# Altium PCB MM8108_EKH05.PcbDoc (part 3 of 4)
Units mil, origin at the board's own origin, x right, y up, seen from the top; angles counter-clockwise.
Board outline 6023.62 x 3425.2 mil, 4 copper layers (Top Layer, Ground Plane, Middle Layer, Bottom Layer), stack 76.15 mil thick; 188 components, 156 nets, 687 pads, 1369 vias.
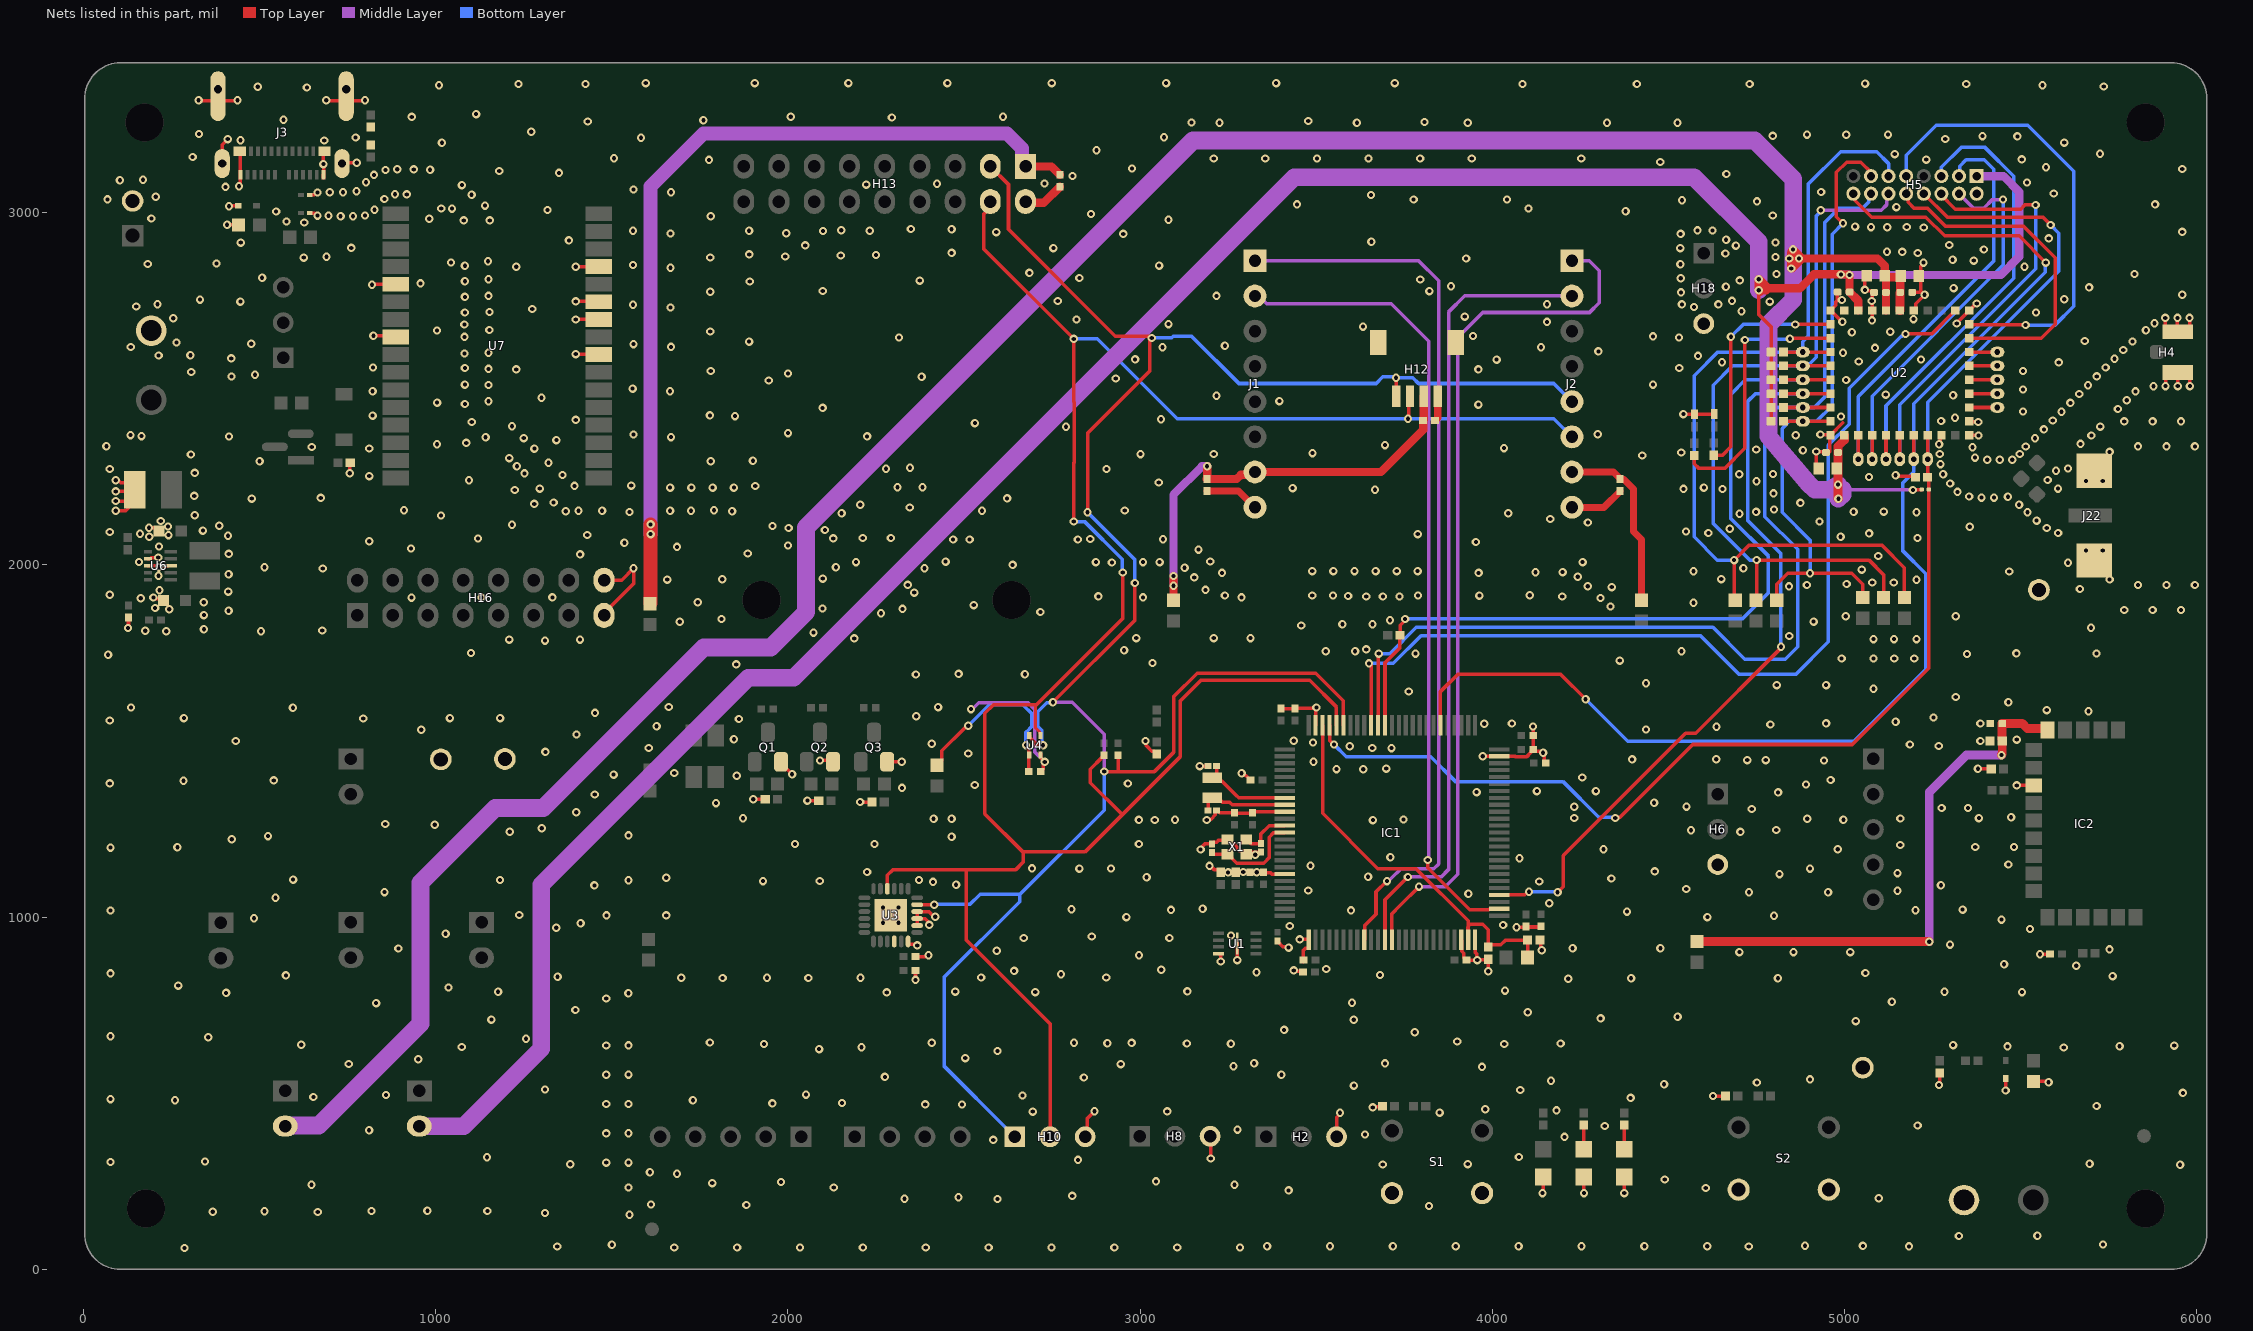
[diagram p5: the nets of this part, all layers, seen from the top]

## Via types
v1: diameter 23.62, hole 11.81, Top Layer to Bottom Layer, tented both sides, 1369 vias

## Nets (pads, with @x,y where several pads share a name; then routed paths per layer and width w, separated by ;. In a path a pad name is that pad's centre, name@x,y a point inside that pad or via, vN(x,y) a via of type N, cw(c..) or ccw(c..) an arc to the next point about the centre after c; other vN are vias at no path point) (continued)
GND: C1.1 C2.1 C3.1 C4.1 C5.1 C6.1 C7.1 C8.1 C9.2 C10.1 C11.1 C12.2 C13.2 C14.1 C15.1 C16.1 C17.1 C18.1 C19.2 C20.2 C21.1 C22.2 C23.2 C24.1 C25.1 C26.1 C27.2 C28.1 C29.2 C30.1 C31.2 C32.2 C33.2 C34.1 C35.1 C36.2 C37.1 C38.1 C39.1 C40.2 C41.1 C42.1 C43.1 C44.2 C45.1 C46.1 C47.1 C48.1 C49.2 D1.K D2.K D3.K D4.A D7.K D11.A D12.A D13.K H2.3 H4.2 H4.3 H5.2 H6.3 H8.3 H10.3 H11.1 H12.4 H12.5 H12.6 H13.2 H14.2 H15.1 H16.15 H16.16 H18.3 IC1.10 IC1.19 IC1.26 IC1.48 IC1.50 IC1.74 IC1.99 IC2.8 J1.8 J2.8 J3.A1 J3.A12 J3.B1 J3.B12 J3.SH1 J3.SH2 J3.SH3 J3.SH4 J22.2 Q1.S Q2.S Q3.S R8.2 R49.2 R52.2 R65.1 R66.1 R67.1 R69.2 R70.2 R72.2 R75.2 S1.3 S1.4 S2.3 S2.4 TP1.1 TP2.1 TP3.1 TP4.1 U1.4 U1.9 U2.1 U2.3 U2.11 U2.20 U2.23 U2.26 U2.30 U2.38 U3.4 U3.6 U3.8 U3.9 U3.10 U3.25 U4.4 U6.2 U6.3 U6.8 U7.5 U7.8 U7.24 U7.26 U7.27 U7.29 VS1.A X1.2 X1.4 | length 7032.6
  Top Layer w10: v1(91.38,2153.74) 120,2153.74 C49.2@145.52,2179.25 ; v1(91.38,2181.3) 133.71,2181.3 145.52,2193.11 129.77,2208.86 v1(91.38,2208.86) ; v1(91.38,2240.35) 93.99,2237.75 100.88,2237.75 105.86,2232.76 120,2232.76 C49.2@146.5,2206.27 ; v1@127.79,1820.2 R72.2@127.79,1850.43 ; C49.2@146.5,2179.25 C49.2@146.5,2206.27 ; U6.3@182.91,1997.36 206.79,1997.36 210.72,1993.43 v1(214.41,1993.43) ; U6.2@182.91,2017.05 189.44,2017.05 192.63,2020.24 211.6,2020.24 v1(212.35,2020.98) ; v1(186.15,2105.38) 204.82,2105.38 C42.1@214.41,2095.79 ; v1(198.28,1907.26) 201.92,1903.62 222.79,1903.62 C41.1@227,1899.41 ; v1@214.41,1991.38 v1(214.41,1993.43) ; U6.8@240,1997.36 239.92,1997.28 219.45,1997.28 215.59,1993.43 v1(214.41,1993.43) ; v1(326.77,3318.9) 327.36,3318.31 436.42,3318.31 v1(437.01,3318.9) ; J3.SH2@393.7,3139.37 393.7,3192.91 v1(409.45,3208.66) ; v1(407.75,2965.55) 439.93,2965.55 C40.2@440.47,2965 ; v1(412.84,3018) 413.83,3018.99 438.37,3018.99 VS1.A@439.36,3019.98 ; v1(441.44,3074.8) 441.44,3078.49 445.16,3082.21 445.16,3106.97 J3.A12@445.67,3107.48 ; J3.A12@445.67,3112.21 J3.B1@445.67,3181.31 ; D12.A@640,3050 D12.A@640.91,3049.09 ; D11.A@642.2,2999.22 643.11,2998.32 656.48,2998.32 662.68,2992.11 v1@666.37,2992.11 ; D12.A@642.2,3050 643.11,3050.91 654.62,3050.91 660.79,3057.07 v1(664.47,3057.07) ; J3.A1@681.1,3098.43 681.38,3098.7 681.38,3106.97 J3.A1@681.89,3107.48 681.41,3107.96 681.41,3137.49 v1(681.1,3137.8) 681.1,3171.65 J3.B12@683.86,3174.41 ; v1(688.98,3318.9) 689.57,3318.31 798.62,3318.31 v1(799.21,3318.9) ; J3.SH1@733.07,3107.28 733.07,3130.71 744.09,3141.73 v1(775.59,3141.73) ; v1(755.76,2260.06) 756.54,2260.85 756.54,2289.22 R75.2@757.32,2290 ; v1@787.43,1566.7 790.32,1563.81 v1(794.01,1563.81) ; R70.2@814.21,3243.46 R70.2@815,3242.68 ; R69.2@815,3192.32 R69.2@820.27,3197.59 ; v1(818.9,2795.28) 820.47,2796.85 U7.5@886.38,2796.85 ; v1(822.83,2650.68) 882.54,2650.68 U7.8@886.38,2646.85 ; v1(1397.64,2598.43) 1461.18,2598.43 U7.24@1462.76,2596.85 ; v1(1397.64,2696.85) U7.26@1462.76,2696.85 ; v1(1397.64,2748.03) 1461.58,2748.03 U7.27@1462.76,2746.85 ; v1(1397.64,2846.46) 1462.36,2846.46 U7.29@1462.76,2846.85 ; H16.15@1477.76,1856.69 1477.76,1862.6 1561.57,1946.42 v1(1561.57,1990.43) 1527.84,1956.69 H16.16@1477.76,1956.69 ; H16.15@1497.1,1849.61 H16.15@1500.25,1846.46 ; v1(1901.57,1334.65) R65.1@1935.43,1334.65 ; Q1.S@1980.33,1440.94 1980.33,1435.69 1997.64,1418.39 1999.14,1418.39 2011.81,1405.72 v1(2011.81,1405.51) ; v1(2055.12,1330.71) R66.1@2087.4,1330.71 ; v1(2090.65,1444.88) 2124.02,1444.88 Q2.S@2127.95,1440.94 ; v1(2204.72,1326.77) R67.1@2238.58,1326.77 ; Q3.S@2281.51,1440.94 v1(2322.83,1440.94) ; U3.6@2341.02,930.98 2341.02,925.25 2342.76,923.5 2359.81,923.5 2363.31,920 v1(2367,920) ; v1(2362,822) C38.1@2362,849 ; C37.1@2362,888 2391.31,888 2395.31,892 v1(2399,892) ; U3.8@2366.61,976.26 U3.9@2366.61,995.94 ; v1(2401,978) 2398.39,980.61 2398.39,986.86 2389.31,995.94 U3.9@2366.61,995.94 ; v1(2418,1001) 2414.31,1001 2400.41,1014.91 2367.33,1014.91 U3.10@2366.61,1015.63 U3.9@2366.61,995.94 ; U4.4@2716.54,1464.57 2717.44,1463.66 2717.44,1451.85 v1@2728.37,1440.92 ; C39.1@2718.11,1413.39 2724.93,1420.2 2724.93,1433.01 2727.7,1435.79 2727.7,1440.25 v1@2728.37,1440.92 ; v1(2728.8,1440.92) v1@2728.37,1440.92 ; H10.3@2848.9,371.72 2848.9,427.64 v1(2870.08,448.82) ; v1(3015.19,1500.19) 3017.61,1497.78 3017.61,1486.52 3033.14,1470.98 3040.04,1470.98 3047.24,1463.78 R8.2@3047.24,1462.99 ; v1(3169.17,1428.67) 3169.4,1428.9 3192.29,1428.9 C25.1@3192.52,1429.13 ; v1(3171.52,1192.19) 3171.52,1195.88 3180.47,1204.83 ; 3180.47,1204.87 3183.67,1208.07 C23.2@3203.74,1208.07 3203.74,1209.65 3207.01,1212.91 3216.85,1212.91 3222.16,1218.22 3245.78,1218.22 X1.4@3248.03,1220.47 3257.8,1210.71 3261.73,1210.71 3267.54,1204.9 3269.32,1204.9 3275.76,1198.45 3275.76,1194.9 3281.77,1188.9 3291.42,1188.9 X1.2@3301.18,1179.13 3306.69,1184.65 C22.2@3342.52,1184.65 ; v1(3188.98,1275.59) 3191.58,1278.2 3201.23,1278.2 3213.36,1290.33 3213.36,1299.88 C26.1@3216.63,1303.15 ; v1(3196.85,1145.67) 3198.99,1145.67 3209.52,1135.14 3221.14,1135.14 3228.35,1127.94 C17.1@3228.35,1127.56 ; v1(3200,315) 3200,363.78 H8.3@3214.17,377.95 ; C26.1@3216.93,1303.15 3218.5,1303.15 3225.13,1296.53 C3.1@3267.72,1296.53 ; U1.4@3222.64,895.67 3228.46,895.67 3228.54,895.59 v1(3228.54,874.21) ; C17.1@3232.28,1127.56 C21.1@3271.65,1127.56 3350.39,1127.56 3351.97,1125.98 3370.08,1125.98 3373.89,1122.17 3409.8,1122.17 IC1.19@3409.92,1122.05 ; C3.1@3267.72,1296.85 3270.08,1294.49 3316.54,1294.49 C2.1@3318.9,1296.85 ; v1(3275.59,877.95) U1.9@3275.59,925.2 ; v1(3287.84,1408.64) 3291.53,1408.64 3299.02,1401.14 3300.86,1401.14 3312,1390 C1.1@3313,1390 ; C2.1@3318.9,1296.53 3321.58,1299.21 IC1.10@3409.92,1299.21 ; C24.1@3389.76,932.68 3389.76,931.1 3404.87,915.99 3418.65,915.99 v1(3421.26,913.39) ; C14.1@3400,1592 C11.1@3440,1592 3441.5,1593.5 3498.5,1593.5 v1(3500,1595) 3498.94,1593.94 3498.94,1545.71 IC1.99@3498.03,1544.8 ; v1(3435.72,848.85) 3438.09,846.48 C5.1@3461.22,846.48 ; v1(3452.76,937.01) 3453.67,937.92 3477.44,937.92 3478.35,937.01 IC1.26@3478.35,935.51 3478.35,912.38 3477.44,911.48 3469.17,911.48 3463.31,905.62 C4.1@3463.31,874.02 ; H2.3@3557.38,376.69 3557.38,432.21 3566.93,441.76 v1(3566.93,444.88) ; v1(3660,460) 3661.3,461.3 3686.1,461.3 C19.2@3687.4,462.6 ; IC1.48@3911.42,935.51 3912.32,934.61 3912.32,903.79 3918.78,897.34 3918.78,885.16 3925.98,877.95 v1(3956.69,877.95) ; IC1.50@3950.79,935.51 3951.69,934.61 3951.69,899.44 3954.76,896.37 3954.76,879.88 v1(3956.69,877.95) ; v1(3972.44,1456.69) IC1.74@4019.21,1456.69 4064.55,1456.69 4066.43,1454.82 4096.42,1454.82 4109.43,1467.82 4109.43,1471.38 4114.43,1476.38 C8.1@4115.43,1476.38 ; v1(3988.19,846.46) C13.2@3988.19,880.31 3987.01,879.13 3957.87,879.13 v1(3956.69,877.95) ; v1(4068.34,971.2) 4068.74,971.59 C7.1@4134.97,971.59 ; C6.1@4100,972.61 4139.61,972.61 C7.1@4140,973 ; v1(4115.09,1541.3) 4115.26,1541.13 4115.26,1515.92 C10.1@4115.43,1515.75 ; C10.1@4115.75,1515.75 4115.75,1476.38 4120.75,1471.38 4135.59,1471.38 4140.05,1466.91 v1(4143.74,1466.91) 4146.35,1464.31 4146.35,1441.84 C15.1@4151.18,1437.01 ; C12.2@4134.45,935.04 4137.45,932.04 4137.45,908.64 v1(4140.05,906.03) ; v1(4141.73,216.54) 4143.7,218.5 D3.K@4143.7,262.2 ; D2.K@4258.86,262.2 4258.86,217.52 v1(4259.84,216.54) ; v1(4374.02,216.54) D1.K@4374.02,262.2 ; v1(4541.97,2428.12) 4542.13,2428.28 4629.36,2428.28 D7.K@4629.53,2428.44 ; v1(4625.98,492.13) C20.2@4661.81,492.13 ; C29.2@4918.96,2283.43 v1(4918.96,2321.88) ; v1@4919.45,2321.4 C30.1@4946.22,2321.4 ; C29.2@4929.79,2283.43 C29.2@4932.78,2280.44 ; v1@4929.79,2321.88 v1@4930.27,2321.4 ; v1(4930.86,2370.17) 4958.57,2370.17 U2.11@4960.14,2368.6 ; C30.1@4957.05,2321.4 4957.05,2365.51 U2.11@4960.14,2368.6 ; C44.2@4979.75,2774.54 4978.57,2773.36 4978.57,2750.29 4974.79,2746.51 4974.79,2737.58 U2.20@4959.65,2722.44 v1@4988.2,2693.89 ; 4994.86,2404 4994.86,2403.33 U2.11@4960.14,2368.6 ; C31.2@5062.18,2812.91 5057.07,2807.81 v1(5057.07,2780.86) 5059.68,2778.26 5077.35,2778.26 C43.1@5082.55,2773.05 ; v1(5077.33,2694.1) 5077.54,2694.31 5077.54,2722.23 U2.23@5077.76,2722.44 C43.1@5077.76,2771.91 ; v1(5144.54,2254.39) 5147.14,2251.78 5198.56,2251.78 C32.2@5200.64,2253.86 ; U2.26@5195.87,2722.44 5201.48,2728.06 5201.48,2741.66 v1(5226.88,2767.06) 5215.22,2778.73 5215.22,2846.06 5223.59,2854.44 v1(5223.59,2858.13) ; C28.1@5198.37,2773.62 5216.64,2773.62 ; v1(5267.72,523.62) 5269.69,525.59 C36.2@5269.69,557.87 ; v1(5267.97,2342.35) 5270.58,2344.95 5270.58,2368.87 U2.3@5273.2,2371.49 ; v1@5324.21,2692.66 5324.21,2693.31 5372.87,2741.96 v1(5374.68,2741.96) ; U2.1@5349.99,2367.9 5350.22,2367.66 5379.1,2367.66 v1(5379.55,2367.22) ; U2.38@5350.3,2406.95 5350.56,2406.69 5378.41,2406.69 v1(5379.2,2405.9) ; v1(5377.95,1421.26) R49.2@5415.75,1421.26 ; v1(5456.69,507.87) D4.A@5456.69,541.34 ; v1(5488.19,1374.02) IC2.8@5536.22,1374.02 ; R52.2@5535.43,533.46 5576.77,533.46 v1(5578.74,531.5) ; v1(5554.29,894.54) 5554.52,894.77 5582.45,894.77 C35.1@5582.68,895 ; v1(5910,2701.22) 5910,2678.07 5925.67,2662.4 H4.2@5944.88,2662.4 ; v1(5910.76,2507.44) 5910.76,2530.59 5926.43,2546.26 H4.3@5944.88,2546.26 ; v1(5944.5,2701.22) 5944.5,2662.78 H4.2@5944.88,2662.4 ; v1(5945.26,2507.44) 5945.26,2545.88 H4.3@5944.88,2546.26 ; v1(5979,2701.22) 5979,2678.07 5963.33,2662.4 H4.2@5944.88,2662.4 ; v1(5979.76,2507.44) 5979.76,2530.59 5964.09,2546.26 H4.3@5944.88,2546.26 ; C49.2@146.5,2193.11 C49.2@146.5,2206.27 ; C49.2@146.5,2193.11 C49.2@146.5,2206.27 ; C49.2@146.5,2193.11 C49.2@146.5,2206.27 ; C49.2@146.5,2193.11 C49.2@146.5,2206.27 ; C49.2@146.5,2193.11 C49.2@146.5,2206.27
  Top Layer w20: C46.1@3188.98,2209.77 3279.4,2209.77 J1.8@3325.59,2163.58 ; C48.1@3837,2410 3838,2410 3844.65,2416.65 H12.4@3844.65,2479 ; J2.8@4225.59,2163.58 4317.02,2163.58 4362.2,2208.77 C47.1@4362.2,2209.77
  Top Layer w23.62: H13.2@2674.41,3031.5 2677.48,3028.43 2726.53,3028.43 C45.1@2771.65,3073.55
  Middle Layer w10: v1(2519.68,1590.55) 2523.37,1590.55 2541.08,1608.26 2681.74,1608.26 2700,1590 2700,1469.72 v1(2728.8,1440.92)
  other v1: 286.55,60.7 1677.17,62.24 1855.64,62.24 2034.12,62.24 2212.6,62.24 2391.08,62.24 2569.55,62.24 2748.03,62.24 2926.51,62.24 3104.99,62.24 3283.46,62.24 1345,65 4727.36,65.11 3360.3,65.54 3538.78,65.54 3717.26,65.54 3895.73,65.54 4074.21,65.54 4252.69,65.54 4431.17,65.54 4609.64,65.54 5182.36,65.4 5051.47,66.91 4887.17,67.35 1500,70 5733.15,70.84 5324.1,94.78 5546.93,95.48 1550,155 1310.31,159.96 665.17,163.15 366.82,163.79 514.08,165.06 817.53,165.7 1146.47,165.7 976.26,166.34 3820,180 1881.89,182.81 1611,184 2595,200 2330.71,200.79 5096.67,202.13 2484.25,204.72 2807.09,208.66 3421.26,224.41 4605.35,231.22 1547.24,232.28 2129.92,232.28 647.23,240.26 3267.72,240.16 1785,245 1980.31,248.03 3045,250 4489.15,255.03 1685.04,271.65 1607.81,275.59 5952.26,297.03 3688.62,297.74 1381.72,298.33 3929.66,298.89 5695.12,300.09 1484.25,303.15 1547.24,303.15 76.54,304.95 344.75,306.3 2823.37,311.05 1145.38,318.25 4075.01,319.11 2582.9,367.67 4204.4,376.3 3637.87,383.09 1484.25,386.28 1547.24,386.39 810.79,395.26 3276.28,396.88 4318.48,407 5206.87,408.76 3850,445 2695.03,447.83 3076.74,448.71 4181.52,451.55 3979.26,454.59 5715.02,463.86 2493.96,467.92 2389.76,468.5 1484.25,469.42 1547.24,469.63 1955.74,471.26 2153.54,472.44 259.77,480.23 1730.03,480.42 76.54,483.43 4392.17,486.84 652.62,489.49 2665.91,493.86 858.78,495.35 2051.18,496.06 5959.94,501.23 4079.01,509.38 1310.02,510.77 3606.53,521.79 4487.35,525.66 4750.61,530.59 4165.86,535.74 4901.57,539.37 2840,545 2275.08,546.52 1484.25,552.55 1547.24,552.87 3400.65,552.8 3970,575 3264.75,576.68 2944.88,582.68 753.19,583.35 3695,585 3323.42,585.44 950.13,596.76 2503.03,599.84 2595,620 2088.47,625.21 5621.73,629.82 2208.76,630.63 1073.68,631.6 5462.09,633.21 5780.4,633.7 5935.68,635.15 1484.25,635.68 1547.24,636.11 5307.78,636.61 618.27,637.77 1932.09,639.76 4033.34,639.87 3257.32,640.49 2906.64,641.86 3132.4,641.36 4193.5,641.38 2407.97,643.29 2975.47,643.19 1778.22,644.25 2811.93,643.46 3900.07,647.06 1256.4,655 354,659 76.54,661.9 3779.53,673.23 3408.42,680 5031.5,704.72 1158,709 3606.3,708.66 4307.09,712.6 4525.52,717.18 4100,730 1396.32,736.49 830.71,755.91 3600.94,756.8 5133.86,759.84 1484.25,769.1 1546.8,784.08 405,785 2280.33,786.57 2701.84,787.21 5503.33,787.03 5283.03,788 1177.05,788.43 2474.76,788.59 3133.86,789.21 4035.43,791.34 1036.45,800.41 269.07,805.53 4215,825 4393.7,826.77 4810.1,826.77 1696.79,827.77 1814.53,827.35 1940.22,828.18 2057.96,827.35 2205.95,828.13 2548.29,828.72 2903.31,828.83 1346,831 5760.51,832.64 574.45,834.74 3680.74,835.85 2775.14,838.04 76.54,840.38 5058.61,841.26 3330.21,843.77 2641.89,847.38 3059.47,850.56 3527.92,852.84 5657.13,861.91 5452.39,866.37 2996.35,891.79 4700.79,900.79 4854.33,900.79 5015.75,900.79 2592.5,904.65 5751.52,908.56 894,911 4227.62,911.67 4476.58,911.87 5299.07,921.94 2669.29,940.94 3082.68,940.94 2862.2,944.88 3257.83,947.83 1028.07,952.94 5525.89,966.35 1342.02,970 3424.4,974.65 4030.12,977.83 1411.26,982.46 2270.15,984.13 2313.46,984.13 5444.8,992.94 483.91,996.88 2960.63,1000 4610,1000 4799.21,1003.94 1485,1005 1654.6,1005 1237.27,1006.23 4381.89,1015.75 76.54,1018.86 3598.41,1019.19 5200.79,1019.68 3087.21,1020.74 5334.75,1021.35 2804.8,1022.54 3177.17,1023.62 2270.15,1027.44 2313.46,1027.44 4161.21,1039.41 545.24,1054.94 3931.5,1066.57 854.59,1071.11 4728.35,1070.87 4952.76,1070.87 5150,1075 3477.1,1075.45 4550,1080 1450.35,1090.17 5272.81,1090.55 2477.32,1092.1 2411.52,1100.13 4132.91,1101.45 1929.13,1102.36 2090.23,1102.39 1547.34,1104.95 1182.21,1105.51 2371.94,1105.58 595.12,1106.46 4337.6,1109.49 1654.6,1111.72 3018.06,1113.34 3646.93,1114.48 4814.96,1122.05 5150,1125 3249.49,1127.22 2224.74,1128.19 3292.43,1128.04 3330.56,1127.49 4460.63,1129.92 2827.19,1137.8 2917.24,1137.94 4901.57,1137.8 2692.64,1138.38 3483.44,1145.69 5464.57,1149.61 4076.84,1167.07 3710,1170 3326.69,1177.16 4314.96,1192.91 4980.31,1192.91 76.54,1197.34 266.41,1198.54 5370.63,1199.21 5480.52,1198.96 5157.48,1204.72 2019.68,1207.81 2245.64,1207.81 2996.06,1207.81 421,1221 2464.57,1228.35 524,1230 1547.34,1232.07 4703.74,1242.13 1209.93,1242.38 4563.62,1246.49 4805.55,1247.38 1301.13,1252.45 997.31,1262.52 856.69,1264.2 2996.14,1276.16 3041.24,1275.59 3660.42,1275.44 3098.68,1276.47 4996.06,1276.4 3747.25,1277.35 2413.39,1279.53 2464.57,1279.53 4893.7,1279.53 5157.88,1279.86 1872.1,1280.56 5380.76,1281.07 4232.28,1281.61 5472.44,1283.46 1398.68,1297.67 4736.22,1307.09 5275,1310 5350,1310 4232.28,1313.29 4550.53,1313.76 1795.61,1323.7 4458.91,1324.8 1451.35,1348.04 3955,1355 4811.02,1354.33 4125.98,1357.68 4293.6,1357.68 2323.66,1367.09 2530.11,1375.18 4890.2,1376.47 74.68,1379.7 2964.78,1379.43 283.67,1387.08 539.93,1388.41 4959.95,1389.39 4254.92,1396.65 1854.33,1401.57 1505.08,1404.5 1677.17,1409.45 3557.16,1420.14 3633.03,1419.85 3698.27,1421.62 3491.76,1441.06 4940.94,1444.88 4723.43,1445.84 4775.76,1445.84 4396.33,1447.83 4635.3,1448.25 2511.81,1464.57 1311.2,1469.21 1604.87,1480.16 3658.51,1480.06 3713.12,1479.77 3595,1485 5266.89,1485.93 5185,1490 2408.31,1492.14 3490.33,1495.59 432.38,1499.94 5385,1500 3435.72,1500.72 5488.19,1503.94 1846.44,1505.25 1399.43,1518.36 959,1532 4435.77,1532.86 4635.84,1540.59 1627,1542 4788.98,1546.72 3976.56,1548.85 4055,1549.92 4947.26,1550.15 5385,1550 5144.57,1554.79 74.68,1558.18 1860.53,1562.5 285,1565 1040,1565 1182.88,1565 5251.97,1566.93 2364.25,1570.25 1452,1580 5692.17,1584.73 5573.65,1587.77 135,1595 594.49,1594.49 2426.13,1596.24 1661.49,1596.66 5464.57,1610.24 5315,1625 3762.06,1640.42 5081.69,1648.62 4807.09,1658.71 4947.26,1658.71 4435.77,1664.04 2363.15,1689.04 2672.51,1689.64 2484.37,1690.54 1853.22,1717.57 3034.85,1721.52 4361.1,1728.35 4991.14,1734.25 5081.69,1734.25 5140.75,1734.25 5197.45,1734.25 70,1745 5347.2,1747.27 3781.48,1748.03 5487.19,1748.78 5714.58,1748.54 1100,1750 3526.58,1754.69 3610,1755 4536.42,1754.92 2954.37,1757.89 3641.58,1760.24 1310,1785 1208.66,1787.81 1409.45,1787.81 5081.69,1789.37 5139.76,1789.37 5203.74,1789.37 2188.33,1791.38 2988.67,1792.15 3208.66,1792.15 3312.81,1792.15 4842.49,1798.03 2072.22,1807.79 234.83,1811.77 504.05,1811.51 175.44,1813.05 677.95,1813.72 341.63,1817.32 126.53,1820.67 5698.98,1821.46 3457.12,1827.83 3573.84,1831.65 3659.41,1831.65 1692.91,1838.58 4911.66,1839.06 3708.86,1842.91 1811.02,1846.46 5002.95,1854.33 5314.96,1854.33 341.63,1857.48 2264.16,1862.59 2716.54,1866.14 411.94,1869.94 5793.31,1872.05 5874.02,1872.05 5954.72,1872.05 243.57,1874.22 2325.05,1875.27 2097.87,1876.18 203.43,1877.54 4335,1881.82 2527.56,1885.83 4570.87,1892.53 341.21,1893.8 1743.94,1893.91 162.32,1905.21 4306.55,1906.08 931.38,1906.98 1130.08,1907.46 1331.15,1907.93 3007.81,1907.81 3287.4,1907.92 4197.85,1910.25 2881.25,1910.61 3641.58,1910.48 3688.83,1910.48 3736.07,1910.48 3590.22,1911.67 3962.83,1912.7 3240.16,1913.39 3488.19,1913.39 3547.24,1913.39 3788.67,1913.39 4105.91,1913.96 74.68,1915.13 2358.27,1921.26 410.97,1924.06 215.76,1927.83 3185.04,1929.13 5667.53,1931.39 4338.58,1937.01 4842.02,1938.95 4270.3,1939.31 2340.2,1943.26 4892.61,1942.83 5832.68,1942.91 5913.39,1942.91 5994.09,1942.91 5005.34,1945.96 5078.14,1950.26 5139.2,1949.87 1657.45,1958.27 5203.74,1957.68 1813.47,1959.13 5751.97,1958.66 4649.61,1959.65 2098.81,1961.01 3153.54,1964.57 4242.11,1966.5 212.74,1969.01 411.98,1973.43 3232.28,1977.42 3960.63,1977.42 4122.29,1979.25 4199.15,1979.59 4570.87,1982.09 5467.14,1981.39 3488.19,1982.42 3548.23,1982.42 3608.27,1982.42 3668.31,1982.42 3728.35,1982.42 3787.4,1982.42 5048.39,1986.67 679.06,1989.84 2387.45,1990.5 4712.27,1990.59 3125.98,1992.13 514.02,1993.17 2136.01,1993.54 2637.8,2000 5633.86,2005.91 2919.56,2007.01 2192.91,2007.87 2874.02,2007.87 3007.81,2007.87 3055.12,2007.87 4255.91,2007.87 157.38,2008.42 2447.44,2009.26 3198.67,2009.69 5094.97,2025.02 1410,2030 412.49,2031.39 1885.98,2032.31 5685.04,2041.34 5732.28,2041.34 3165.35,2043.31 929.96,2046.41 1685.04,2051.18 214.41,2052.48 2000,2055.12 1535.43,2062.99 3952.81,2065 811.02,2066.93 2468.88,2071.94 2515.75,2072.05 2822.83,2072.05 3064.87,2072.62 2858.22,2073.73 1120,2075 2128.56,2075.37 2212.09,2076.21 2292.02,2076.2 5206.4,2076.14 186.61,2080.1 4988.39,2080.04 410,2082.58 241.3,2084.46 1430,2085 3788.02,2087.27 160.27,2088.25 5069.29,2089.62 4612.87,2090.62 5605.78,2090.33 74.68,2093.61 4549.6,2095 338.99,2097.29 2104.75,2099.21 4673.7,2102.66 2001.86,2104.53 5573.47,2104.88 5354.99,2108.15 240.04,2108.82 385.55,2111.02 1956.24,2110.69 1216.54,2114.17 4270.69,2120.25 4928.15,2123.03 219.17,2124.72 5544.8,2125.7 4164.17,2130.29 1015,2140 315.63,2140.87 4701.28,2145.02 2152.38,2146.83 4044.68,2146.41 1550,2150 5203.54,2149.69 5518.69,2149.66 4748.37,2150.63 5025.16,2150.92 5110.77,2151.12 1369.03,2152.45 1841.47,2152.32 1405.51,2153.54 1472.44,2153.54 1665.35,2153.54 1724.41,2153.54 2550.83,2153.89 2955.85,2154.27 910,2155 1790,2155 4799.24,2157.12 2345.86,2162.98 2205.22,2170.66 5495.19,2170.56 1279.53,2173.23 4873.96,2176.18 1334.65,2177.17 477.47,2188.11 2622.05,2188.98 673.52,2190.33 5388.39,2190.91 5423.82,2190.91 5353.1,2194.13 5463.15,2193.47 314.42,2195.9 4798.02,2203.02 5320.23,2207.34 1224.41,2212.6 3666.68,2213.32 4652.95,2215.28 4542.39,2215.82 1295.28,2216.54 5605.62,2216.53 3432.69,2217.88 1665.35,2219.27 1725.72,2219.27 1786.09,2219.27 1846.46,2219.27 4600.21,2219.32 2311.02,2220.47 2381.89,2220.47 1907.05,2224.12 1393.7,2224.41 1555,2225 5299.13,2231.1 3052.6,2234.04 4749.35,2237.44 5685.04,2238.19 5732.28,2238.19 1094.49,2240.16 5575.92,2241.17 5068.68,2249.41 811.02,2251.97 1360,2255 4700.36,2257.46 4796.33,2258.26 5279.4,2257.58 1251.97,2259.84 315.63,2261.22 5599.95,2267.22 74.68,2272.09 2904,2272.2 2278.36,2272.82 5633.86,2273.62 2346.46,2275.59 1230.36,2280.12 5271.91,2286.12 1320,2290 500.13,2294.19 1780.76,2294.4 1900.35,2295.71 5404.58,2298.51 5440.01,2298.51 5475.44,2298.51 1208.66,2303.15 5369.67,2304.58 4425.04,2310.36 304.74,2313.22 3000.55,2314.44 3208.66,2314.96 5269.89,2314.78 5496.75,2315.07 3488.82,2317.33 4535.88,2319.01 5751.97,2320.87 4881.11,2325.34 4748.92,2327.4 1280,2330 811.02,2330.71 4032.63,2331.59 5362.79,2334.21 648.05,2334.6 5514.03,2335.93 64.98,2336.7 5832.68,2336.61 5913.39,2336.61 5994.09,2336.61 3695,2340 1003.55,2342.52 5669.29,2343.61 1086.61,2346.46 1342.52,2354.33 1250,2360 5540.28,2359.73 1141.73,2362.2 1667.74,2362.74 413.19,2364.56 2224.63,2364.95 164.87,2365.52 4861.1,2368.11 5700.17,2367.44 133.62,2368.4 1561.55,2370.39 4298.9,2370.75 2000,2374.02 5565.34,2384.79 2789.21,2392.27 5725.22,2392.49 1216.54,2393.7 2530.53,2402.44 1102.36,2405.51 5273.7,2408.28 5793.31,2407.48 5874.02,2407.48 5954.72,2407.48 5590.39,2409.84 1397.52,2411.7 3059.06,2413.39 5313.22,2417.65 4989.38,2421.47 1849.46,2422.37 820.84,2423.86 1778.13,2424.51 5615.45,2434.9 5505.91,2435.64 5775.33,2442.6 2098.42,2445.78 3960,2455 1082.68,2456.69 5640.5,2459.95 1003.94,2460.63 1149.61,2464.57 3395,2465 5800.39,2467.66 1300.21,2474.32 3216.54,2480.31 5307.7,2481.55 5116.23,2483.49 5665.56,2485.01 820.94,2492.97 1665.11,2492.84 5825.44,2492.71 5506.24,2498.03 1558.93,2500.5 5876.44,2507.28 5690.61,2510.06 1149.61,2510.5 1082.68,2511.81 4455.71,2511.81 1945.46,2523.51 5004.07,2525.07 2930.47,2529.27 2379.46,2533.92 420.21,2534.92 5715.67,2535.12 487.05,2539.86 2000,2543.31 306,2547.61 1780.76,2550.67 5505.91,2550.4 1228.35,2555.12 3960,2555 1149.61,2556.43 1082.68,2559.06 4530.13,2559.1 5740.72,2560.17 822.11,2560.57 5607.48,2574.87 4651.54,2575.3 5039.83,2577.22 4011.81,2582.68 5216.26,2583.16 2985.39,2583.51 5765.78,2585.23 419.54,2586.35 4583.4,2593.48 213.28,2594.37 303.33,2595.03 1081.46,2600.19 4995.24,2602.13 1149.61,2602.36 4300.52,2606.28 5790.83,2610.28 5085.68,2616.06 3062.99,2618.11 4137.8,2618.11 134.34,2618.72 1667.74,2619.01 3240.16,2622.05 1561.55,2626.66 476.31,2627.76 264.19,2631.26 1889.76,2633.86 5816.76,2634.43 5681.46,2635.85 2314.96,2645.67 4529.27,2645.46 1081.46,2647.43 4455.71,2648.72 3944.88,2649.61 5020.26,2660.66 5129.16,2662.06 1779.45,2662.37 1003.55,2665.35 5855,2666.22 1152.35,2666.67 3632.19,2676.47 1081.22,2682.23 3080.36,2683.42 5317.83,2685.23 5879.46,2686.23 4155,2690 4993.4,2690.37 2818.9,2696.85 5195.13,2697.68 255,2700 3921.26,2704.72 1082.68,2716.54 5542.79,2716.35 1152.62,2718.11 4707.02,2720.27 1274.13,2726.51 1666.43,2730.71 4572.24,2732.02 149.84,2733.81 1560.24,2738.37 210,2740 4155,2740 4537.68,2739.67 4641.36,2739.67 445.41,2747.45 4786.97,2747.5 2765.9,2749.27 5076.57,2749.09 4679.82,2749.53 4991.78,2752.06 330.99,2753.01 5623.03,2754.05 1082.68,2760.83 1149.61,2763.78 3216.54,2763.78 5958.26,2766.88 4535.02,2773.61 1779.45,2775.39 2098.59,2777.79 3820.71,2777.29 5309.24,2785.84 5693.83,2787.96 4662.46,2789.52 3882.18,2791.25 956.69,2799.21 1082.68,2805.12 1891.62,2804.51 2374.02,2807.09 4701.91,2807.87 3795,2810 1149.61,2811.02 4534.41,2813.98 507.17,2815 2827.2,2814.44 4806.05,2825.7 5822.6,2825.97 2685.34,2828.95 1666.43,2843.73 5510.32,2846.21 1228.35,2846.46 1082.68,2849.41 3053.61,2849.67 1560.24,2851.39 4533.49,2853.74 182.26,2854.35 377.7,2855.65 1043.31,2858.27 1148.4,2862.2 5366.46,2863.72 5306.39,2866.42 3925.2,2870.08 625.31,2872.34 1779.45,2872.64 690,2875 4803.24,2874.35 1992.31,2875.63 2149.58,2878.51 2250,2880 1889.93,2881.6 4661.18,2883.93 5207.43,2885.24 2464.57,2885.83 5120.14,2888.96 5163.19,2888.66 5394.88,2895.4 760,2900 2753.39,2899.32 4532.88,2899.31 2048.86,2907.18 4690.9,2906.34 5296.86,2908.34 446.46,2914.99 4803.63,2915.02 3656.21,2917.5 1377.95,2921.26 4663.32,2922.91 5579.31,2927.02 2951.73,2939.75 4534.1,2939.68 1666.43,2940.98 1995.18,2941.35 2591.42,2944.67 5958.26,2945.35 2099.15,2947.87 1560.24,2948.64 1889.76,2948.82 2232.28,2948.82 2151.38,2949.96 4581.94,2949.78 4624.76,2949.48 2464.57,2952.76 2348.91,2953.52 5224.39,2957.96 5074.68,2958.84 5120.7,2958.46 5175.98,2959.42 5029.43,2960.36 626.85,2971.91 576.2,2975.01 1079.65,2978.1 1153.25,2978.18 3080,2980 192.59,2983.2 981.57,2982.55 730,2990 765,2990 1780.76,2989.61 664.53,2991.45 695.71,2991.36 799.05,2991.92 4795.73,2991.68 2860.26,2996 546.88,3003.31 4377.95,3003.94 826.14,3008.12 1317.11,3007.78 1015.7,3011.96 1046.24,3011.51 4102.36,3011.81 5146.67,3015.74 1140,3020 3444.88,3023.62 5881.08,3023.46 4751.02,3032.02 4537.94,3035.28 68.07,3037.82 3776.21,3037.5 4041.21,3037.5 854.07,3038.57 205,3045 3655,3050 1101.8,3050.62 884.51,3052.25 917.75,3051.97 5593.15,3054.15 699.19,3057.9 736.9,3057.9 1667.74,3057.94 4932.94,3058.59 775.16,3060.69 1561.55,3065.6 403.05,3073.19 1074.24,3078.18 2222.34,3079.53 2423.25,3082.17 2728.35,3082.68 5517.49,3085.48 802.2,3086.38 103.31,3091.86 168.7,3093.54 2807.56,3104.18 824.75,3107.28 4663.89,3109.78 1349.97,3112.91 1180.44,3118.17 857.55,3121.3 984.08,3121.86 890.66,3123.2 937.71,3122.98 5958.26,3123.83 2976.8,3125.21 5571.14,3128.85 4476.38,3143.84 1775.5,3149.94 5231.36,3150.44 5502.38,3151.31 3208.66,3153.54 3355.12,3153.54 3501.57,3153.54 3648.03,3153.54 3794.49,3153.54 3940.94,3153.54 4251.97,3153.54 1506.09,3154.37 309.92,3157.83 5141.8,3166.11 5724.61,3167.01 2876,3177 1017.48,3198.33 5622.99,3198.69 683.37,3204.8 445.52,3205.44 5285.13,3209.14 1582.68,3212.6 772.48,3213.33 3067.35,3213.9 5490.16,3216.54 4795.73,3217.9 5390.85,3217.35 5004.3,3220.94 4892.91,3221.57 5122.78,3221.41 327.72,3223.12 1271.12,3229.87 3225,3255 3615,3255 3930,3255 4325,3255 4525,3255 3145.67,3255.91 3806.79,3257.51 1431.45,3258.79 3476.84,3259.98 1759.84,3262.22 567.92,3263.76 2295,3270 932.05,3271.93 2007.87,3272.19 2610.24,3272.19 1114.73,3279.81 634.06,3355.07 494.65,3357.25 5735.54,3358.31 1009.36,3361.65 5561.47,3361.65 1235,3365 1425,3365 4085,3365 4410,3365 4730,3365 5345,3365 5057.82,3366.3 1596.28,3367.81 1905.48,3367.81 2171.32,3367.81 2452.46,3367.81 2748.91,3367.81 3073.4,3367.75 3385.83,3367.75 3722.39,3367.75
I2C_SCL: H10.1 H12.1 H13.3 IC1.95 J2.5 R82.2 U3.11 U4.2 | length 6493.4
  Top Layer w10: U3.11@2366.61,1035.31 2414.68,1035.31 v1(2415,1035) ; H13.3@2574.41,3131.5 2625.98,3079.92 2625.98,2952.76 2929.13,2649.61 3027.56,2649.61 v1@3027.56,2644.29 ; U4.2@2685.04,1515.75 2685.94,1514.84 2685.94,1510.91 2707.42,1489.43 2723.03,1489.43 v1(2724.27,1488.19) ; v1(2751.97,1610.24) 2985,1843.27 2985,1948.67 v1(2984.84,1948.83) ; v1(2850.39,2149.61) 2850.39,2374.02 3027.56,2551.18 v1@3027.56,2644.29 ; v1(2897.64,1413.39) 2937.01,1413.39 ; R82.2@2937.01,1459.38 2937.01,1413.39 ; v1(3032.88,2644.29) v1@3027.56,2644.29 ; IC1.95@3576.77,1544.8 3576.77,1614.17 3498.03,1692.91 3161.42,1692.91 3094.49,1625.98 3094.49,1467.51 3040.36,1413.39 2937.01,1413.39 ; v1(3725.85,2531.18) 3726.19,2530.84 3726.19,2479.34 H12.1@3726.54,2479
  Middle Layer w10: v1(2751.97,1610.24) 2807.09,1610.24 2897.64,1519.69 v1(2897.64,1413.39)
  Bottom Layer w10: v1(2415,1035) 2416,1036 2516,1036 2545.5,1065.5 2657.93,1065.5 2657.93,1043.93 2443,829 2443,577.39 2629.92,390.47 H10.1@2657.48,390.47 ; 2657.93,1064.27 2897.64,1303.98 v1(2897.64,1413.39) ; v1(2724.27,1488.19) 2721.67,1490.8 2721.67,1499.66 2720.47,1500.86 2720.47,1529.91 2708.79,1541.59 2708.79,1567.08 2708.79,1582.81 2734.38,1608.39 2750.13,1608.39 v1(2751.97,1610.24) ; v1(2850.39,2149.61) 2985,2015 2985,1948.98 v1(2984.84,1948.83) ; v1(3032.88,2644.29) 3088.46,2644.29 3093.78,2649.61 3145.67,2649.61 3280.28,2515 3670,2515 3688.78,2533.78 3723.24,2533.78 v1(3725.85,2531.18) 3726.35,2531.68 3773.32,2531.68 3790,2515 4174.17,2515 J2.5@4225.59,2463.58
I2C_SDA: H10.2 H12.2 H13.4 IC1.96 J2.6 R85.2 U3.16 U4.1 | length 6810.3
  Top Layer w8: 2702.56,1603.27 2702.56,1600.2 2702.56,1537.6 2714.63,1525.53 2714.63,1521.59 U4.1@2716.54,1519.68
  Top Layer w10: U3.16@2281.96,1080.59 2281.96,1118.96 2297,1134 2505.92,1134 ; H13.4@2574.41,3031.5 2574.41,3014.5 2555.12,2995.2 2555.12,2897.64 v1(2811.02,2641.73) 2811.02,2463.39 2812.02,2462.39 2812.02,2290.34 2811.02,2289.34 v1(2811.02,2123.14) ; 2667.35,1185 2667.35,1155.59 2645.75,1134 2505.92,1134 ; 2702.56,1600.2 2950.18,1847.82 v1(2950.18,1978.48) ; 2702.56,1603.27 2583.58,1603.27 2559.06,1578.74 2559.06,1293.01 2667.06,1185 2843.02,1185 3114.17,1456.16 3114.17,1614.17 3172.42,1672.42 3481.12,1672.42 3557.09,1596.46 IC1.96@3557.09,1544.8 ; H10.2@2744.09,380.66 2744.09,696.85 2505.92,935.02 2505.92,1134 ; R85.2@2897.64,1459.38 2897.64,1458.38 2892.64,1453.38 2891.64,1453.38 2858.27,1420.01 2858.27,1381.89 2947.25,1292.91 ; v1(3760,2415) 3762.61,2417.61 3762.61,2475.7 H12.2@3765.91,2479
  Bottom Layer w10: v1(2811.02,2123.14) 2841.86,2123.14 2948.54,2016.46 2948.54,1980.11 v1(2950.18,1978.48) ; v1(2811.02,2641.73) 2878.27,2641.73 3105,2415 v1(3760,2415) 4174.17,2415 J2.6@4225.59,2363.58
LED_G: R17.1 U2.19 | length 668.9
  Top Layer w10: R17.1@4628.08,2311.24 4653.12,2311.24 4676.83,2334.96 v1(4676.83,2647.87) ; v1(4859.73,2682.52) 4860.28,2683.07 U2.19@4959.65,2683.07
  Bottom Layer w10: v1(4676.83,2647.87) 4711.48,2682.52 v1(4859.73,2682.52)
LED_R: R21.1 U2.18 | length 749.3
  Top Layer w10: R21.1@4572.58,2310.73 4572.58,2287.53 4586.29,2273.82 4659.25,2273.82 4716.6,2331.18 4716.6,2468.06 v1(4716.6,2638.63) ; v1(4844.28,2641.87) 4845.19,2642.79 4958.73,2642.79 U2.18@4959.65,2643.7
  Bottom Layer w10: v1(4716.6,2638.63) 4718.22,2640.25 4842.66,2640.25 v1(4844.28,2641.87)
MIKRO_AN: IC1.34 J1.1 | length 2561.3
  Top Layer w10: IC1.34@3635.83,935.51 3636.73,936.42 3636.73,975.9 3669.29,1008.46 3669.29,1071.93 3699.72,1102.36 v1(3700.79,1102.36)
  Middle Layer w10: J1.1@3325.59,2863.58 3789.96,2863.58 3847.03,2806.51 3847.03,1151.06 3833.76,1137.8 3740.16,1137.8 3711.54,1109.17 3711.28,1109.17 3704.47,1102.36 v1(3700.79,1102.36)
MIKRO_INT: IC1.37 J2.2 | length 2281.6
  Top Layer w10: IC1.37@3694.88,935.51 3694.88,1049.21 v1(3759.84,1114.17)
  Middle Layer w10: v1(3759.84,1114.17) 3854.33,1114.17 3875.31,1135.15 3875.31,2717.83 3921.06,2763.58 J2.2@4225.59,2763.58
MIKRO_PWM: IC1.38 J2.1 | length 2453.9
  Top Layer w10: IC1.38@3714.57,935.51 3714.57,1009.84 3736.89,1032.17 v1(3791.34,1086.61)
  Middle Layer w10: v1(3791.34,1086.61) 3866.14,1086.61 3901.59,1122.06 3901.59,2645.69 3972.44,2716.54 4275.59,2716.54 4303.15,2744.09 4303.15,2834.65 4274.21,2863.58 J2.1@4225.59,2863.58
MIKRO_RST: IC1.52 J1.2 | length 2296.6
  Top Layer w10: v1(3816.26,1162.1) 3816.26,1140.07 3935.49,1020.84 3989.32,1020.84 3991.19,1022.72 4018.31,1022.72 IC1.52@4019.21,1023.62
  Middle Layer w10: J1.2@3325.59,2763.58 3336.91,2763.58 3358.95,2741.55 3712.8,2741.55 3819.26,2635.08 3819.26,1174.73 3818.87,1174.34 3818.87,1164.71 v1(3816.26,1162.1)
MM_BUSY: IC1.91 U2.29 | length 2736
  Top Layer w10: v1(3649.61,1720.47) 3655.51,1714.57 IC1.91@3655.51,1544.8 ; v1(5172.49,2655.7) 5247.23,2655.7 U2.29@5313.98,2722.44
  Bottom Layer w10: v1(3649.61,1720.47) 3718.41,1720.47 3797.15,1799.21 4590.55,1799.21 4700.79,1688.98 4861.22,1688.98 4953.6,1781.35 4953.6,2340.3 5012.5,2399.2 5012.5,2501.24 5160.77,2649.51 5162.62,2649.51 5168.81,2655.7 v1(5172.49,2655.7)
MM_DBG_RX: H5.9 U2.31 | length 1326.9
  Top Layer w10: U2.31@5353.35,2683.07 5354.37,2682.05 5512.54,2682.05 v1(5513.57,2681.03)
  Bottom Layer w10: H5.9@5174.41,3103.74 5174.41,3162.6 5259.84,3248.03 5519.69,3248.03 5649.95,3117.76 5649.95,2734.07 5596.91,2681.03 v1(5513.57,2681.03)
MM_DBG_TX: H5.10 U2.32 | length 959.8
  Top Layer w10: H5.10@5178.76,3057.73 5179.8,3056.69 5179.8,3029.63 5196.33,3013.11 5233.85,3013.11 5284.95,2962.01 5506.74,2962.01 5597.14,2871.61 5597.14,2683.4 5557.44,2643.7 U2.32@5353.35,2643.7
MM_GPIO_3: U2.21
MM_GPIO_6: pad.31@5433.07,2604.33 U2.33 | length 77.4
  Top Layer w10: U2.33@5353.35,2604.33 pad.31@5430.73,2604.33
MM_GPIO_7: pad.31@5433.07,2564.96 U2.34 | length 91.5
  Top Layer w10: U2.34@5353.35,2564.96 pad.31@5444.88,2564.96
MM_GPIO_8: pad.31@5433.07,2525.59 U2.35 | length 91.5
  Top Layer w10: U2.35@5353.35,2525.59 pad.31@5444.88,2525.59
MM_GPIO_9: pad.31@5433.07,2486.22 U2.36 | length 91.5
  Top Layer w10: U2.36@5353.35,2486.22 pad.31@5444.88,2486.22
MM_GPIO_10: pad.31@5433.07,2446.85 U2.37 | length 91.5
  Top Layer w10: U2.37@5353.35,2446.85 pad.31@5444.88,2446.85
MM_JTAG_TCK: H5.5 pad.31@5117.13,2300.2 U2.7 | length 1299.9
  Top Layer w10: pad.31@5117.13,2309.06 U2.7@5117.13,2368.11
  Bottom Layer w10: pad.31@5117.13,2300.2 5117.13,2451.77 5479.57,2814.22 5479.57,3103.81 5398.35,3185.04 5330.71,3185.04 5274.41,3128.74 H5.5@5274.41,3103.74
MM_JTAG_TDI: H5.3 pad.31@5038.39,2300.2 U2.9 | length 1185.7
  Top Layer w10: pad.31@5038.39,2309.06 U2.9@5038.39,2368.11
  Bottom Layer w10: pad.31@5038.39,2300.2 5038.39,2477.95 5423.08,2862.65 5423.08,3122.93 5395.93,3150.09 5344.42,3150.09 5326.28,3131.94 5326.28,3105.61 H5.3@5324.41,3103.74
MM_JTAG_TDO: H5.4 pad.31@5077.76,2300.2 U2.8 | length 1102.7
  Top Layer w10: pad.31@5077.76,2309.06 U2.8@5077.76,2368.11
  Middle Layer w10: H5.4@5324.41,3053.74 5365.5,3012.65 5394.93,3012.65 5419.5,3037.22 v1(5449.08,3037.22)
  Bottom Layer w10: pad.31@5077.76,2300.2 5077.76,2479.21 5450.23,2851.68 5450.23,3036.06 v1(5449.08,3037.22)
MM_JTAG_TMS: H5.6 pad.31@5156.5,2300.2 U2.6 | length 1232.3
  Top Layer w10: pad.31@5156.5,2309.06 U2.6@5156.5,2368.11 ; H5.6@5272.26,3051.59 5313.68,3010.16 5499.6,3010.16 5511.35,3021.91 v1(5542.04,3021.91)
  Bottom Layer w10: pad.31@5156.5,2300.2 5156.5,2455 5542.04,2840.54 v1(5542.04,3021.91)
MM_RESET_N: C32.1 H5.8 IC1.97 pad.31@5235.24,2300.2 R16.1 U2.4 | length 3894.5
  Top Layer w10: IC1.97@3537.4,1544.8 3537.4,1502.6 v1(3550,1490) ; v1(4348.31,1281.61) 4350.92,1284.22 4362.96,1284.22 4568.9,1490.16 5021.65,1490.16 5125.98,1594.49 5238.39,1706.89 5238.39,2223.42 ; H5.8@5224.41,3053.74 5291.59,2986.55 5563,2986.55 v1(5584.45,2965.11) ; U2.4@5235.24,2368.11 5235.24,2298.23 5235.24,2261.07 C32.1@5236.66,2259.65 ; 5238.19,2223.42 C32.1@5238.19,2253.86
  Bottom Layer w10: v1(3550,1490) 3585,1455 3825,1455 3895,1385 4200,1385 4301.54,1283.46 4346.46,1283.46 v1(4348.31,1281.61) ; pad.31@5235.24,2298.23 5235.24,2461.44 5607.75,2833.96 5607.75,2941.8 v1(5584.45,2965.11)
MM_SDIO_CLK: H5.11 pad.31@4880.91,2604.33 R15.2 R31.2 R41.1 U2.17 | length 2604.6
  Top Layer w10: R31.2@4687.49,1893.12 4685.98,1894.63 v1(4685.98,2013.54) 4727.61,2055.16 5106.25,2055.16 5169.29,1992.13 R41.1@5169.29,1907.48 ; R15.2@4825.79,2604.33 pad.31@4880.91,2604.33 U2.17@4959.65,2604.33
  Bottom Layer w10: v1(4685.98,2013.54) 4638.51,2013.54 4572.41,2079.65 4572.41,2537.48 4639.26,2604.33 pad.31@4880.91,2604.33 ; pad.31@4885.09,2604.33 pad.31@4880.91,2604.33 ; H5.11@5124.41,3103.74 5124.41,3139.37 5090.55,3173.23 4988.19,3173.23 4897.06,3082.1 4897.06,2649.78 4880.91,2633.62 pad.31@4880.91,2604.33
MM_SDIO_CMD: H5.12 pad.31@4880.91,2564.96 R14.2 R32.2 R42.1 U2.16 | length 2225.8
  Top Layer w10: R32.2@4748.03,1899.61 4749.98,1901.56 v1(4749.98,2013.87) 5068.8,2013.87 5110.24,1972.44 R42.1@5110.24,1907.48 ; R14.2@4825.79,2564.96 pad.31@4880.91,2564.96 U2.16@4959.65,2564.96
  Middle Layer w10: v1(4931.87,3006.87) 4932.23,3006.5 5103.37,3006.5 5118.67,3021.81 5118.67,3048 H5.12@5124.41,3053.74
  Bottom Layer w10: v1(4749.98,2013.87) 4730.22,2013.87 4626.69,2117.41 4626.69,2510.21 4681.44,2564.96 4892.47,2564.96 4898.55,2571.05 4900.61,2571.05 4919.26,2589.7 4919.26,2990.58 4931.87,3003.18 v1(4931.87,3006.87)
MM_SDIO_D0: H5.13 pad.31@4880.91,2407.48 R13.2 R33.2 R43.1 U2.12 | length 1904.3
  Top Layer w10: R33.2@4807.09,1899.61 4807.09,1944.88 4838.58,1976.38 v1(4901.57,1976.38) 5019.69,1976.38 5051.18,1944.88 R43.1@5051.18,1907.48 ; R13.2@4825.79,2407.48 pad.31@4880.91,2407.48 U2.12@4959.65,2407.48 ; v1(4994.88,2969.99) 4976.38,2988.5 4976.38,3114.57 5005.25,3143.44 5045.54,3143.44 H5.13@5074.41,3114.57
  Bottom Layer w10: v1(4901.57,1976.38) 4901.57,2070.21 4822.1,2149.69 4822.1,2387.06 4842.52,2407.48 pad.31@4880.91,2407.48 4919.85,2407.48 4964.06,2451.69 4964.06,2939.16 v1(4994.88,2969.99)
MM_SDIO_D1: IC1.54 pad.31@4880.91,2486.22 R12.2 U2.14 | length 2181.9
  Top Layer w10: IC1.54@4019.21,1062.99 4090.8,1062.99 4093.2,1065.39 4093.32,1065.39 4100.13,1072.2 v1(4103.82,1072.2) ; v1(4185.04,1070.87) 4200.79,1086.61 4200.79,1174.98 4548.1,1522.29 4577.16,1522.29 4818.9,1764.03 v1(4818.9,1767.72) ; R12.2@4825.79,2486.22 pad.31@4880.91,2486.22 U2.14@4959.65,2486.22
  Bottom Layer w10: v1(4103.82,1072.2) 4183.71,1072.2 v1(4185.04,1070.87) ; v1(4818.9,1767.72) 4818.9,2031.61 4724.09,2126.41 4724.09,2463.79 4746.52,2486.22 pad.31@4880.91,2486.22
MM_SDIO_D2: IC1.89 pad.31@4880.91,2525.59 R3.2 R11.2 U2.15 | length 2351
  Top Layer w10: IC1.89@3694.88,1544.8 3694.88,1722.44 3737.32,1764.88 R3.2@3737.32,1800 3738.11,1800.79 3738.11,1828.91 3751.97,1842.77 v1(3751.97,1846.46) ; R11.2@4825.79,2525.59 pad.31@4880.91,2525.59 U2.15@4959.65,2525.59
  Bottom Layer w10: v1(3751.97,1846.46) 4708.66,1846.46 4783.46,1921.26 4783.46,2025.15 4675.76,2132.86 4675.76,2483.29 4718.06,2525.59 pad.31@4880.91,2525.59
MM_SDIO_D3: H5.14 IC1.90 pad.31@4880.91,2446.85 R10.2 U2.13 | length 3171.8
  Top Layer w10: IC1.90@3675.2,1544.8 3676.1,1545.71 3676.1,1746.97 v1(3677.17,1748.03) ; R10.2@4825.79,2446.85 pad.31@4880.91,2446.85 U2.13@4959.65,2446.85
  Bottom Layer w10: v1(3677.17,1748.03) 3708.86,1748.03 3783.66,1822.83 4625.98,1822.83 4716.54,1732.28 4830.71,1732.28 4866.14,1767.72 4866.14,2044.31 4773.24,2137.21 4773.24,2431.3 4788.8,2446.85 pad.31@4880.91,2446.85 4913.39,2446.85 4943.23,2476.7 4943.23,2972.16 4984.18,3013.11 5051.62,3013.11 5068.67,3030.16 5068.67,3048 H5.14@5074.41,3053.74
MM_VBAT: C27.1 C28.2 C29.1 C30.2 C31.1 C43.2 H19.2 R16.2 U2.10 U2.24 U2.25 | length 7992.2
  Top Layer w10: v1(5193.39,2212.84) 5193.96,2213.41 5218.15,2213.41 R16.2@5218.61,2213.87
  Top Layer w23.62: v1(4842.52,2870.08) v1@4848.11,2870.08 ; v1(4848.11,2841.27) v1@4848.11,2870.08 ; v1@4850.67,2841.33 4850.67,2841.75 v1@4878.99,2870.08 ; C31.1@5114.35,2819.8 5114.35,2833.15 5113.85,2833.64 5113.85,2849.13 5092.9,2870.08 v1@4878.99,2870.08 ; U2.24@5117.13,2722.44 C43.2@5117.13,2773.62 C31.1@5117.13,2812.91 ; v1@4848.11,2870.08 4848.11,2883.15 cw(c4865.92,2883.15) v1(4853.33,2895.75) v1@4878.99,2870.08 ; v1@4848.11,2870.08 v1(4870.08,2870.08) v1@4878.99,2870.08
  Top Layer w25: v1(4982.03,2187.61) 4980.78,2188.86 v1(4980.78,2227.85) 4981.01,2228.08 4981.01,2336.64 4999.02,2354.64 U2.10@4999.02,2368.11 ; C31.1@5117.13,2812.91 5120.62,2816.41 5157.15,2816.41 5157.48,2816.08 C28.2@5157.48,2773.62 5156.5,2772.64 U2.25@5156.5,2722.44
  Middle Layer w10: 5007.26,2212.84 v1(5193.39,2212.84)
  Middle Layer w50: H19.2@572.83,406.69 574.57,408.43 667.94,408.43 956.69,697.18 956.69,1097.69 1169,1310 1305,1310 1760.62,1765.62 1950.66,1765.62 2051.18,1866.14 2051.18,2106.18 3149.72,3204.72 4744.09,3204.72 4853.33,3095.49 v1(4853.33,2895.75) ; v1@4854.33,2895.75 4854.33,2753.28 4783.46,2682.41 4783.46,2364.96 4898.51,2229.03 4914.62,2212.92 4956.04,2212.92 v1(4980.78,2227.85) ; v1(4982.03,2187.61) 4993.57,2199.15 4993.57,2215.05
MM_VDDIO: C44.1 H3.2 H5.1 R10.1 R11.1 R12.1 R13.1 R14.1 R15.1 U2.22 | length 7138.8
  Top Layer w10: v1(4755.91,2779.53) 4755.91,2710.69 4791.14,2675.45 R13.1@4791.14,2407.48
  Top Layer w23.62: C44.1@5013.75,2782.52 C44.1@5013.75,2774.54 5038.39,2749.9 U2.22@5038.39,2722.44 ; C44.1@5013.76,2782.54 v1(5013.76,2823.02) 5012.17,2824.62 v1(4989.03,2824.62) 4988.66,2824.99 4912.36,2824.99 4872.63,2785.26 4782.81,2785.26 ; v1(4755.91,2779.53) v1@4760.03,2779.53 ; v1(4755.91,2779.53) 4760.03,2775.4 v1@4760.03,2779.53 ; v1(4755.91,2779.53) v1(4755.91,2811.02) 4757.05,2811.02 4782.38,2785.69 ; v1@4760.03,2779.53 4777.09,2779.53 4782.81,2785.26 ; v1@4760.03,2779.53 4760.03,2783.65 4762.07,2785.69 4782.38,2785.69 ; 4782.38,2785.69 4782.81,2785.26
  Middle Layer w23.62: v1(4989.03,2824.62) 4989.3,2824.35 5012.43,2824.35 v1(5013.76,2823.02) 5443.5,2823.02 5495.45,2874.97 5495.45,3058.82 5450.53,3103.74 H5.1@5374.41,3103.74
  Middle Layer w50: H3.2@953.41,406.69 1079.92,406.69 1299.21,625.98 1299.21,1092.04 1887.17,1680 2016.4,1680 3437.43,3101.03 4572.2,3101.03 4755.98,2917.24 v1@4755.98,2811.1 ; v1(4755.91,2779.53) v1(4755.91,2811.02)
MM_WAKE: H5.16 IC1.81 pad.31@5195.87,2300.2 U2.5 | length 3700.5
  Top Layer w10: IC1.81@3852.36,1544.8 3852.38,1640.42 3900.94,1688.98 4194.07,1688.98 v1(4264.46,1618.59) ; H5.16@5024.41,3053.74 5030.15,3048 5030.15,3034.21 5076.98,2987.38 5230.4,2987.38 5283.86,2933.92 5495.06,2933.92 v1(5570.84,2858.13) ; pad.31@5195.87,2309.06 U2.5@5195.87,2368.11
  Bottom Layer w10: v1(4264.46,1618.59) 4383.57,1499.48 5025.94,1499.48 5230.31,1703.86 5230.31,1974.41 5165.35,2039.37 5165.35,2233.27 5195.87,2263.78 pad.31@5195.87,2300.2 5195.87,2457.65 5569.54,2831.32 5569.54,2856.83 v1(5570.84,2858.13)
NetC12_1: C12.1 C13.1 IC1.49 IC1.98 L1.1 | length 1125.6
  Top Layer w10: IC1.98@3517.72,1544.8 3517.72,1294.64 3674.78,1137.57 3782.9,1137.57 3931.1,989.37 3931.1,974.41 3937.01,980.31 3972.44,980.31 3988.19,964.57 C13.1@3988.19,914.96 3994.49,921.26 4023.62,921.26 4037.4,935.04 C12.1@4099.8,935.04 L1.1@4099.8,885.83 ; 3930.51,971.07 3930.51,936.11 IC1.49@3931.1,935.51
NetC22_1: C22.1 IC1.12 X1.3 | length 150.4
  Top Layer w10: X1.3@3301.18,1220.47 3303.15,1220.47 3314.57,1209.06 C22.1@3342.52,1209.06 3342.52,1236.22 3366.14,1259.84 IC1.12@3409.92,1259.84
NetC23_1: C23.1 IC1.13 X1.1 | length 295.1
  Top Layer w10: C23.1@3203.74,1183.66 3203.74,1182.4 3207.01,1179.13 X1.1@3248.03,1179.13 3250,1179.13 3259.76,1169.37 3259.76,1167.4 3273.8,1153.37 3350.22,1153.37 3366.14,1169.29 3366.14,1227.19 3378.2,1239.25 3409.02,1239.25 IC1.13@3409.92,1240.16 ; C23.1@3203.74,1183.96 C23.1@3207.01,1187.23
NetC25_2: C25.2 IC1.8 X2.2 | length 266
  Top Layer w10: X2.2@3204.72,1395.67 3207.17,1395.67 3216.93,1405.43 3216.93,1425.87 C25.2@3213.36,1425.87 ; X2.2@3208.66,1397.64 3220.39,1385.91 3232.2,1385.91 3271.41,1346.7 3279.53,1338.58 IC1.8@3409.92,1338.58
NetC26_2: C26.2 IC1.9 X2.1 | length 255.3
  Top Layer w10: C26.2@3192.52,1303.15 3192.52,1328.82 3202.28,1338.58 X2.1@3204.72,1338.58 3214.49,1328.82 3231.09,1328.82 3233.14,1326.77 3252.85,1326.77 3260.72,1318.9 IC1.9@3409.92,1318.9
NetC33_1: C33.1 C34.2 IC2.5 R47.2 | length 1560.6
  Top Layer w25: R47.2@4580.71,931.1 5238.9,931.1 v1(5240,930) ; v1(5445,1460) 5447.32,1462.32 C33.1@5447.32,1505 ; C33.1@5446.67,1505 5446.67,1549.67 C34.2@5447,1550 5504.01,1550 5518.41,1535.61 5571.48,1535.61 IC2.5@5575.59,1531.5
  Middle Layer w25: v1(5240,930) 5240,1355 5345,1460 v1(5445,1460)
NetC39_2: C39.2 R54.2 U4.3 | length 543.2
  Top Layer w10: R54.2@2423.23,1431.1 2436.63,1444.5 2436.63,1472.06 2501.06,1536.5 2501.31,1536.5 2508.12,1543.31 v1(2511.81,1543.31) ; v1(2675.64,1488.44) 2675.64,1484.75 2684.13,1476.26 2684.13,1461.54 U4.3@2685.04,1460.63 2683.46,1459.06 C39.2@2683.46,1413.39
  Bottom Layer w10: v1(2511.81,1543.31) 2571.77,1603.27 2666.61,1603.27 2692.79,1577.08 2692.79,1576.91 2692.66,1576.78 2692.66,1541.61 2685,1533.95 2685,1533.64 2675.64,1524.28 v1(2675.64,1488.44)
NetC45_2: C45.2 H13.1 R55.2 | length 2506.4
  Top Layer w23.62: H13.1@2674.41,3131.5 2674.73,3131.17 2748.03,3131.17 C45.2@2771.65,3107.55
  Top Layer w40: v1(1610,2115) 1610,1891.97 R55.2@1610.24,1891.73
  Middle Layer w40: v1(1610,2087.44) v1(1610,2115) 1610,3074.57 1759.84,3224.41 1908.23,3224.41 2622.05,3224.41 2664.88,3181.57 2664.88,3141.02 H13.1@2674.41,3131.5
NetC46_2: C46.2 C48.2 H12.3 J1.7 R61.2 | length 1261.6
  Top Layer w23.62: R61.2@3094.49,1899.61 v1(3094.49,1940.94) v1(3094.49,1968.5) ; v1(3190,2280) 3190,2244.8 C46.2@3188.98,2243.77 3273.77,2243.77 3285.67,2255.67 3317.67,2255.67 J1.7@3325.59,2263.58 3683.58,2263.58 3803,2383 C48.2@3803,2410 3805.28,2412.28 H12.3@3805.28,2479
  Middle Layer w23.62: v1(3094.49,1940.94) v1(3094.49,1968.5) 3094.49,2199.49 3175,2280 v1(3190,2280)
NetC47_2: C47.2 J2.7 R60.1 | length 521.1
  Top Layer w20: J2.7@4225.59,2263.58 4343.39,2263.58 4362.2,2244.77 C47.2@4362.2,2243.77 4362.2,2242.77 4372.83,2242.77 4400,2215.6 4400,2095 4423.23,2071.77 R60.1@4423.23,1899.61
NetD1_A: D1.A R4.2 | length 68.9
  Top Layer w10: D1.A@4374.02,340.94 R4.2@4374.02,409.84
NetD2_A: D2.A R5.2 | length 68.9
  Top Layer w10: D2.A@4258.86,340.94 R5.2@4258.86,409.84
